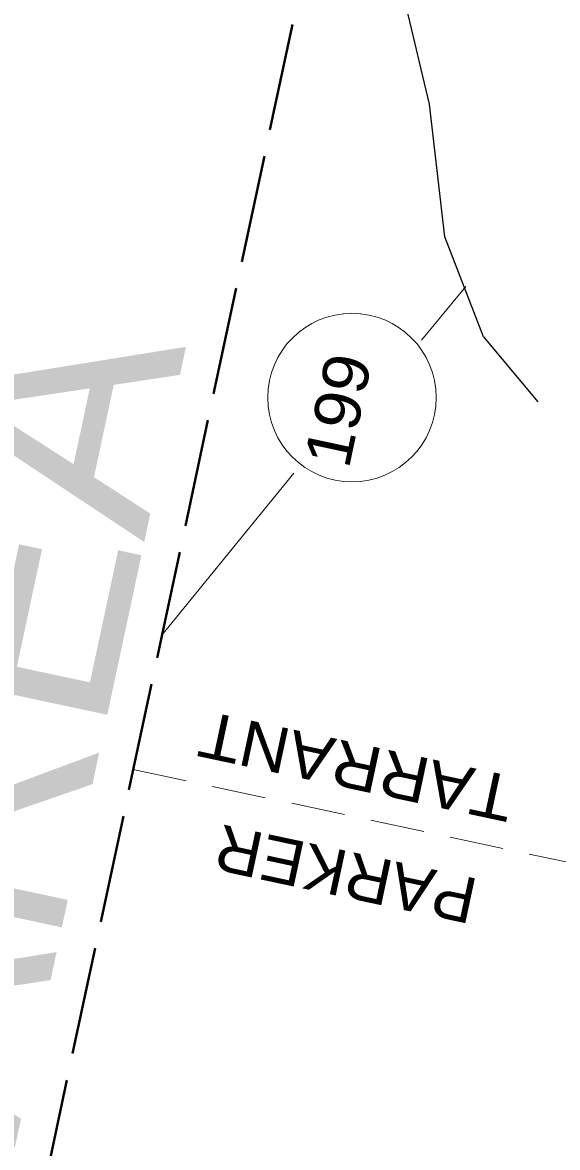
# Model space of a CAD drawing. Extents: x 2363411 to 2369126, y 6976878 to 6988319.
# Drawn here: x 2365871.2 to 2365930.7, y 6976977 to 6977102.1 of the extents above; entities that cross this region are included whole.
import ezdxf

# ---------------------------------------------------------------- set-up
doc = ezdxf.new("R2010")
doc.units = 0
doc.header["$LTSCALE"] = 2
doc.linetypes.add('LONG_DASHED', pattern=[7.5, 6, -1.5])
doc.linetypes.add('MEDIUM_DASHED', pattern=[4.5, 3, -1.5])
doc.layers.add('62', color=7, linetype='Continuous', lineweight=13)
doc.layers.add('63', color=7, linetype='Continuous', lineweight=13)

msp = doc.modelspace()

# ---------------------------------------------------------------- linework, layer by layer
at = {"layer": '62'}
for p, q in [((2365915.551, 6977066.756), (2365920.491, 6977072.742)), ((2365886.709, 6977033.961), (2365901.377, 6977051.998))]:
    msp.add_line(p, q, dxfattribs=at)
at = {"layer": '62', "lineweight": 25}
msp.add_line((2365922.442, 6977067.124), (2365928.474, 6977059.921), dxfattribs=at)
at = {"layer": '62', "linetype": 'MEDIUM_DASHED'}
msp.add_line((2365883.523, 6977019.043), (2366065.134, 6976980.263), dxfattribs=at)
at = {"layer": '62', "lineweight": 25}
msp.add_lwpolyline([(2365922.442, 6977067.124), (2365918.148, 6977078.257), (2365916.442, 6977093.003), (2365913.887, 6977103.765), (2365911.492, 6977114.516), (2365909.362, 6977127.375), (2365908.054, 6977134.719), (2365910.142, 6977144.49), (2365913.476, 6977160.09), (2365917.048, 6977171.753), (2365921.041, 6977176.974), (2365924.542, 6977179.148)], dxfattribs=at)
at = {"layer": '62', "linetype": 'LONG_DASHED', "lineweight": 40}
msp.add_lwpolyline([(2365804.964, 6976956.79), (2365867.37, 6976943.454), (2365903.697, 6977113.468), (2365841.291, 6977126.802), (2365804.897, 6976956.481)], dxfattribs=at)
at = {"layer": '62'}
msp.add_circle((2365907.826, 6977060.389), 9.364, dxfattribs=at)
at = {"layer": '63'}
for p, q in [((2365915.551, 6977066.756), (2365920.491, 6977072.742)), ((2365886.709, 6977033.961), (2365901.377, 6977051.998))]:
    msp.add_line(p, q, dxfattribs=at)
at = {"layer": '63', "lineweight": 25}
msp.add_line((2365922.442, 6977067.124), (2365928.474, 6977059.921), dxfattribs=at)
at = {"layer": '63', "linetype": 'MEDIUM_DASHED'}
msp.add_line((2365883.523, 6977019.043), (2366065.134, 6976980.263), dxfattribs=at)
at = {"layer": '63', "lineweight": 25}
msp.add_lwpolyline([(2365922.442, 6977067.124), (2365918.148, 6977078.257), (2365916.442, 6977093.003), (2365913.887, 6977103.765), (2365911.492, 6977114.516), (2365909.362, 6977127.375), (2365908.054, 6977134.719), (2365910.142, 6977144.49), (2365913.476, 6977160.09), (2365917.048, 6977171.753), (2365921.041, 6977176.974), (2365924.542, 6977179.148)], dxfattribs=at)
at = {"layer": '63', "linetype": 'LONG_DASHED', "lineweight": 40}
msp.add_lwpolyline([(2365804.964, 6976956.79), (2365867.37, 6976943.454), (2365903.697, 6977113.468), (2365841.291, 6977126.802), (2365804.897, 6976956.481)], dxfattribs=at)
at = {"layer": '63'}
msp.add_circle((2365907.826, 6977060.389), 9.364, dxfattribs=at)

# ---------------------------------------------------------------- texts
at = {"layer": '62'}
for s, height, rotation, width, p in [('AREA', 23.83, 77.939, 1.05, (2365870.348, 6976976.988)), ('199', 5.099, 77.939, 1.1, (2365907.452, 6977052.332)), ('TARRANT', 5.099, 167.939, 1.1, (2365926.178, 6977018.165)), ('PARKER', 5.099, 167.939, 1.05, (2365922.053, 6977006.829))]:
    msp.add_text(s, height=height, rotation=rotation, dxfattribs=dict(at, width=width)).set_placement(p)
at = {"layer": '63'}
for s, height, rotation, width, p in [('AREA', 23.83, 77.939, 1.05, (2365870.348, 6976976.988)), ('199', 5.099, 77.939, 1.1, (2365907.452, 6977052.332)), ('TARRANT', 5.099, 167.939, 1.1, (2365926.178, 6977018.165)), ('PARKER', 5.099, 167.939, 1.05, (2365922.053, 6977006.829))]:
    msp.add_text(s, height=height, rotation=rotation, dxfattribs=dict(at, width=width)).set_placement(p)

doc.saveas('drawing.dxf')
